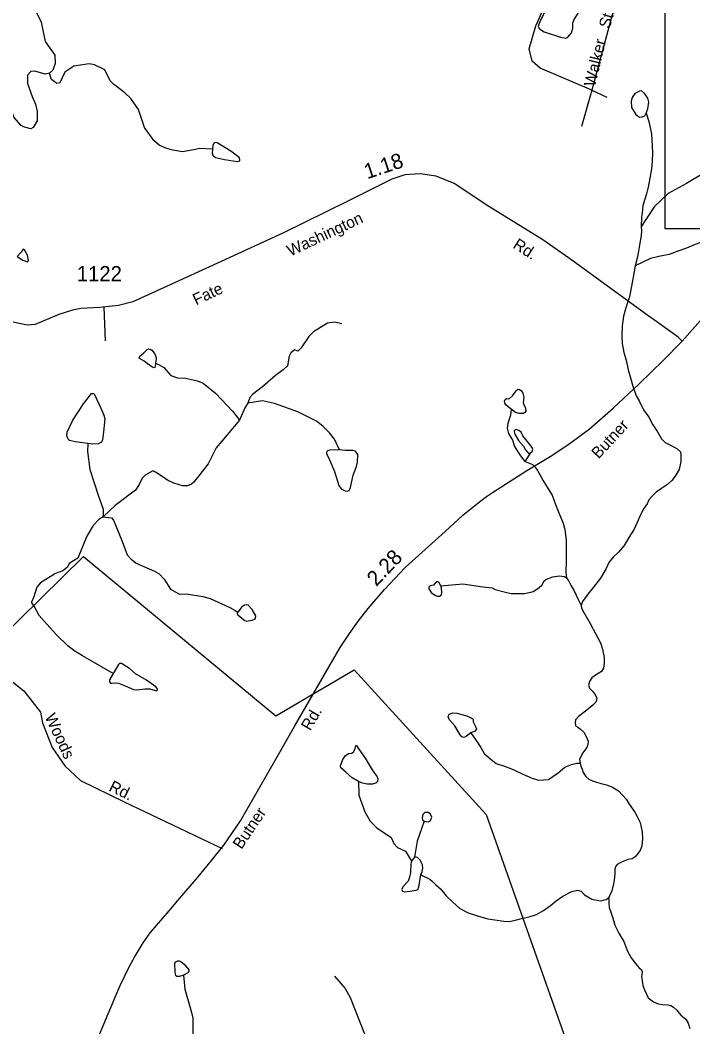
# Model space of a CAD drawing. Extents: x 2056842 to 2160602, y 826753 to 1016856.
# Drawn here: x 2070531 to 2076067, y 880850 to 889134 of the extents above; entities that cross this region are included whole.
import ezdxf

# ---------------------------------------------------------------- set-up
doc = ezdxf.new("R2010")
doc.units = 0
for name, color, linetype in [('Exist Boundary Land Use Reservation Military US Department of Defense', 7, 'Continuous'), ('Exist Hydrographic Creek Single Shore', 7, 'Continuous'), ('Exist Hydrographic Misc Water Feature', 7, 'Continuous'), ('Exist Road Non-System Type 51', 7, 'Continuous'), ('Exist Road Non-System Type 51 Label', 7, 'Continuous'), ('Exist Road Secondary Mileage Hundredths English Label', 7, 'Continuous'), ('Exist Road Secondary Type 51 Attributed', 7, 'Continuous'), ('Exist Road Secondary Type 51 Label', 7, 'Continuous'), ('Exist Road Secondary Type 51 Number Label', 7, 'Continuous'), ('Map Preparation Inset Cut Line', 7, 'Continuous')]:
    doc.layers.add(name, color=color, linetype=linetype)

msp = doc.modelspace()

# ---------------------------------------------------------------- linework, layer by layer
at = {"layer": 'Exist Boundary Land Use Reservation Military US Department of Defense'}
msp.add_lwpolyline([(2070346.7, 884029), (2071050.9, 884719.7), (2072633.6, 883408.7), (2073279.7, 883788.5), (2074366.8, 882597), (2075240.6, 880122.7)], dxfattribs=at)
at = {"layer": 'Exist Hydrographic Creek Single Shore'}
for points in [[(2070649.1, 889230.1), (2070703.2, 889116.2), (2070735.5, 888958.3), (2070815.8, 888844.4), (2070820, 888776.3), (2070800.1, 888722.3), (2070772.1, 888696.3)], [(2070772.1, 888696.3), (2070736, 888690.2), (2070652.1, 888714.2), (2070620, 888710), (2070592.2, 888680), (2070591.9, 888611.5), (2070628.6, 888506.4), (2070657.7, 888441.8), (2070670.4, 888382.2)], [(2070670.4, 888382.2), (2070671.7, 888304.9), (2070637.5, 888250.5), (2070619.7, 888240.3), (2070566.9, 888252.1), (2070538.8, 888265.8), (2070478.6, 888335.9), (2070443.7, 888441.8), (2070398.2, 888469.6), (2070341.2, 888465.8), (2070286.6, 888470.6)], [(2075682.4, 888367.8), (2075703.6, 888299.2), (2075726.5, 888197.5), (2075735.1, 888045.6), (2075731, 887969.5), (2075725.2, 887909.6), (2075711.7, 887833.7), (2075699.8, 887759.6), (2075684, 887703.5), (2075673.8, 887667.4), (2075656.1, 887609.6), (2075648.3, 887545.4), (2075644.2, 887513.2), (2075640.7, 887433.3)], [(2075640.7, 887433.3), (2075644.8, 887401.4), (2075640.7, 887357.5), (2075631.3, 887297.2), (2075619.2, 887233.3), (2075609.6, 887175.1), (2075591.7, 887113.3)], [(2075591.7, 887113.3), (2075574.3, 887018.9), (2075546.4, 886857.2), (2075514.8, 886767), (2075494.9, 886698.6), (2075485.3, 886616.9), (2075481.2, 886536.8), (2075483.7, 886472.7), (2075499.9, 886398.8), (2075518.1, 886334.8), (2075534.5, 886256.8), (2075552.6, 886189.2), (2075573.1, 886121.1), (2075599.1, 886043.3), (2075625.4, 886001.2), (2075659.4, 885927.4), (2075703.9, 885865.5), (2075737.7, 885803.6), (2075776.1, 885745.8), (2075808.1, 885687.8), (2075838.4, 885658.1), (2075878.4, 885640.2), (2075934.6, 885610.2), (2075964.5, 885580.5), (2075966.4, 885556.7), (2075966.8, 885500.6), (2075952.8, 885436.6), (2075921.3, 885382.5), (2075893.2, 885344.2), (2075857.3, 885312.3), (2075809.5, 885279.8), (2075765.4, 885249.9), (2075731.6, 885217.7), (2075703.7, 885185.4), (2075689.7, 885153.5), (2075663.9, 885115.6), (2075638.1, 885069.6), (2075584.6, 884945.4), (2075540.7, 884875.4), (2075500.9, 884810.8), (2075455, 884756.9), (2075411.5, 884714.8), (2075375.2, 884670.8), (2075353.7, 884622.6), (2075305.5, 884540.6), (2075250.1, 884468.3), (2075202.1, 884410.1), (2075158.7, 884350.2), (2075148.6, 884318.1)], [(2073177.2, 886633.4), (2073121.3, 886647.2), (2073061.2, 886639.3), (2072945.3, 886568.7), (2072905.5, 886530.6), (2072843.4, 886436.5), (2072815.3, 886410.7), (2072791.5, 886420.4), (2072759.6, 886396.5), (2072743.8, 886368.4), (2072732.1, 886290.3), (2072696.2, 886256.3), (2072632, 886210.1), (2072526.2, 886116.2), (2072442.3, 886053.7), (2072422.2, 886029.6), (2072404.4, 885981.7)], [(2072404.4, 885981.7), (2072380.2, 885943.9), (2072336.9, 885841.7)], [(2072336.9, 885841.7), (2072189.3, 885669.4), (2072145, 885615.2), (2072079.2, 885483.2), (2071959.4, 885330.8), (2071939.8, 885315.1), (2071907.8, 885301), (2071867.8, 885301), (2071795.8, 885324.9), (2071747.6, 885346.8), (2071643.7, 885414.5), (2071623.6, 885424.4), (2071559.8, 885390.3), (2071535.4, 885364.4), (2071511.4, 885312.4), (2071480, 885266), (2071311.9, 885139.7), (2071214.1, 885045.4)], [(2074683.6, 885500.6), (2074722.3, 885486.8), (2074746.1, 885478.1), (2074768.9, 885454.7), (2074789, 885426.8), (2074809, 885388.9), (2074833.2, 885348.7), (2074861.5, 885298.9), (2074907.5, 885225), (2074936.2, 885149.3), (2074968, 885065.3), (2075000.2, 884993.5), (2075012.3, 884943.4), (2075019, 884899.3), (2075022.9, 884851.6), (2075022.9, 884767.6), (2075023.1, 884679.6), (2075021.9, 884587.6), (2075026, 884543.6)], [(2071214.1, 885045.4), (2071178.2, 885023.7), (2071130.9, 884974.1), (2071080.8, 884887.5), (2071004.9, 884707.5), (2070935.2, 884661.2), (2070919.2, 884631.2), (2070882.9, 884603), (2070821.2, 884579.1), (2070697.9, 884504.1), (2070667.5, 884468.6), (2070642.2, 884387.6), (2070623.2, 884344.5)], [(2073993.9, 884479), (2074172.6, 884494), (2074338.2, 884471.3), (2074414.1, 884461.9), (2074440.2, 884449.8), (2074524.2, 884426.1), (2074572.2, 884416), (2074606.3, 884416.2), (2074638.2, 884414.5), (2074680.3, 884416.7), (2074720.3, 884422.8), (2074752.2, 884433), (2074782.4, 884450.7), (2074802.1, 884464.8), (2074824.2, 884485), (2074841.9, 884519.2), (2074857.8, 884531), (2074913.8, 884553.4), (2074965.7, 884561.3), (2075009.8, 884555.4), (2075026, 884543.6)], [(2075026, 884543.6), (2075037.9, 884527.6), (2075046.1, 884515.8), (2075066, 884477.9), (2075085.9, 884443.7), (2075126.3, 884360), (2075148.6, 884318.1)], [(2075148.6, 884318.1), (2075150.9, 884297.9), (2075158.5, 884278), (2075221, 884168.3), (2075269.2, 884082.3), (2075307.5, 884008.8), (2075323.9, 883956.7), (2075337.9, 883890.4), (2075335.8, 883842.5), (2075330.1, 883800.3), (2075314.5, 883772.7), (2075288.3, 883758.4), (2075264.5, 883742.5), (2075236.6, 883720.4), (2075216.5, 883692.2), (2075208.5, 883662.1), (2075216.5, 883636.2), (2075242.9, 883608.3), (2075262.8, 883582.4), (2075277.2, 883558.5), (2075274.9, 883538.5), (2075266.9, 883522.7), (2075247, 883498.5), (2075210.9, 883470.3), (2075183.1, 883448.1), (2075125.6, 883404.1), (2075101.5, 883376.1), (2075097.4, 883352), (2075101.9, 883328.1), (2075119.9, 883316.1), (2075141.8, 883298.1), (2075169.7, 883276), (2075189.6, 883240.1), (2075203.8, 883200.2), (2075202.1, 883174.2), (2075194.3, 883148.1), (2075162.4, 883104.3), (2075136.3, 883057.9), (2075134.7, 883050), (2075138.6, 883018.2)], [(2074240, 883269.2), (2074284.3, 883205.4), (2074322.3, 883147.3), (2074348.3, 883099.6), (2074390.7, 883063.9), (2074448.6, 883017.7), (2074516.8, 882994.1), (2074589, 882968.4), (2074668.6, 882928.8), (2074743.2, 882896.8), (2074796.7, 882878.9), (2074879, 882885.2), (2074913.2, 882909.2), (2074956.9, 882939.5), (2075012.5, 882987.8), (2075066.6, 883009.6), (2075110.5, 883020.1), (2075138.6, 883018.2)], [(2075138.6, 883018.2), (2075144.9, 882994.2), (2075155, 882970.3), (2075165, 882944), (2075187.1, 882909.8), (2075210.9, 882888.3), (2075240.9, 882874.5), (2075272.9, 882862.7), (2075312.9, 882852.6), (2075357.2, 882842.6), (2075404.9, 882820.8), (2075453.5, 882793.1), (2075487.4, 882757.1), (2075517.5, 882723.4), (2075543.5, 882681.2), (2075587.8, 882615.7), (2075607.7, 882579.4), (2075631.7, 882531.6), (2075648.3, 882455.6), (2075652.4, 882395.7), (2075646.5, 882339.8), (2075632.5, 882299.7), (2075602.8, 882263.7), (2075591.1, 882247.6), (2075566.7, 882233.4), (2075530.8, 882227.5), (2075492.9, 882211.4), (2075467.1, 882199.1), (2075443.1, 882185.2), (2075433, 882172.9), (2075425.2, 882149), (2075425.4, 882116.9), (2075421.3, 882074.9), (2075413.3, 882027), (2075399.8, 881969), (2075380.1, 881929), (2075374, 881912.9)], [(2073827.6, 882099.5), (2073901.7, 882063.9), (2073923.8, 882046.4), (2073950.1, 882020.5), (2073989.9, 881986.4), (2074036.4, 881928.7), (2074092, 881874.8), (2074148.4, 881822.8), (2074218.5, 881787.4), (2074294.4, 881763.7), (2074380.7, 881737.7), (2074436.7, 881730), (2074510.9, 881718.3), (2074558.5, 881716.4), (2074616.5, 881730.7), (2074668.6, 881744.7), (2074720.9, 881754.6), (2074780.8, 881774.8), (2074836.3, 881807.3), (2074896.4, 881849.3), (2074941.9, 881885.4), (2074996.3, 881925.5), (2075069.7, 881963.9), (2075117.7, 881974), (2075147.2, 881966.3), (2075174.6, 881935), (2075234.6, 881900), (2075305.8, 881887.5), (2075338.3, 881894.8), (2075354.3, 881898.9), (2075374, 881912.9)], [(2075374, 881912.9), (2075376.2, 881880.8), (2075374.2, 881864.9), (2075378.1, 881833.1), (2075392.2, 881792.9), (2075408.6, 881742.9), (2075424.8, 881686.8), (2075461.3, 881615.2), (2075497.4, 881551.3), (2075527.3, 881479.3), (2075559.5, 881417.6), (2075593.6, 881371.6), (2075621.5, 881337.6), (2075643.6, 881319.7), (2075648.1, 881305.7), (2075650.2, 881298.1), (2075643.8, 881267.7), (2075648.1, 881229.8), (2075656.3, 881189.9), (2075668.2, 881154), (2075684.4, 881117.9), (2075698.6, 881087.8), (2075742.6, 881054.4), (2075780.8, 881038.4), (2075816.7, 881034.2), (2075861, 881032.3), (2075886.6, 881026.4), (2075906.5, 881012.8), (2075931.1, 880988.8), (2075969, 880946.9), (2076009.2, 880912.9), (2076029.1, 880881.1), (2076041.4, 880835)], [(2073119, 881265.6), (2073205.1, 881165.6), (2073247.2, 881091.9), (2073363.8, 880792.2)]]:
    msp.add_lwpolyline(points, dxfattribs=at)
at = {"layer": 'Exist Hydrographic Misc Water Feature'}
msp.add_line((2074727.3, 885569.3), (2074683.6, 885500.6), dxfattribs=at)
for points in [[(2074816.7, 889137.7), (2074798, 889100.2), (2074794.3, 889081.5), (2074804.2, 889062.8), (2074844.1, 889037.8), (2074976.4, 888994.1), (2075020, 888985.4), (2075038.7, 888994.1), (2075067.4, 889030.3), (2075079.9, 889067.8), (2075079.9, 889110.2), (2075091.1, 889140.2), (2075127.3, 889198.8), (2075126.1, 889212.6), (2075117.3, 889220), (2075071.2, 889232.5), (2075006.3, 889256.2), (2074942.7, 889291.2), (2074919, 889302.4), (2074912.8, 889302.4), (2074905.3, 889294.9), (2074871.6, 889245), (2074816.7, 889137.7)], [(2072112.6, 888073.1), (2072006.8, 888077), (2071974.4, 888068.9), (2071866.8, 888050.7), (2071786.8, 888064.5), (2071730.8, 888080.3), (2071674.6, 888106.2), (2071630.5, 888142.2), (2071554.1, 888249.9), (2071506.1, 888398), (2071442.1, 888487.7), (2071393.5, 888536), (2071299.6, 888607.5), (2071271.7, 888635.6), (2071227.6, 888723.5), (2071143.1, 888767.2), (2071099.5, 888773.3), (2070971.5, 888755), (2070899.3, 888704.6), (2070857.7, 888616.9), (2070833.5, 888612.8), (2070787.8, 888646.5), (2070771.4, 888696.5)], [(2075682.4, 888367.8), (2075697.4, 888404), (2075704.9, 888458.9), (2075697.4, 888492.6), (2075667.5, 888531.3), (2075645, 888551.3), (2075627.5, 888550), (2075590.1, 888531.3), (2075566.4, 888496.4), (2075558.9, 888466.4), (2075562.7, 888415.2), (2075597.6, 888356.6), (2075626.3, 888336.6), (2075648.7, 888337.9), (2075671.2, 888346.6), (2075682.4, 888367.8)], [(2072112.6, 888073.1), (2072110, 888040.2), (2072115.1, 888023.7), (2072139.2, 888002.2), (2072212.6, 887986.9), (2072318.9, 887971.7), (2072339.2, 887976.8), (2072339.2, 887986.9), (2072332.9, 888003.4), (2072265.8, 888055.4), (2072151.8, 888123.8), (2072135.4, 888126.3), (2072124, 888121.2), (2072116.4, 888101), (2072112.6, 888073.1)], [(2076494, 887999.4), (2076460.3, 887985.6), (2076379.2, 887950.7), (2076350.5, 887940.7), (2076272, 887922), (2076156.4, 887873.3), (2076013, 887789.7), (2075863.3, 887707.3), (2075752.1, 887601.5), (2075668.6, 887475.4), (2075640.7, 887433.3)], [(2076163.2, 887313.9), (2076086.9, 887288.6), (2076013.3, 887256.4), (2075951.2, 887236.1), (2075871.4, 887204), (2075787.8, 887187.9), (2075717.2, 887173.4), (2075591.7, 887113.3)], [(2070592.4, 887200.3), (2070566.5, 887244.4), (2070554.4, 887248.3), (2070538.2, 887224.4)], [(2070538.2, 887224.4), (2070506.6, 887188.2), (2070552.2, 887158.1)], [(2070552.2, 887158.1), (2070592.4, 887144.3), (2070600.4, 887154.5), (2070592.4, 887200.3)], [(2071644.3, 886311.7), (2071643, 886288.3), (2071639.9, 886274.4), (2071632.9, 886273.1), (2071619, 886276.9), (2071589.8, 886298.4), (2071550.6, 886326.3), (2071512, 886349.7), (2071510.7, 886358), (2071515.8, 886368.7), (2071548.1, 886394.7), (2071576.5, 886423.9), (2071588.6, 886428.9), (2071601.2, 886427), (2071615.8, 886417.5), (2071637.3, 886389.6), (2071648.7, 886364.9), (2071650, 886345.9), (2071644.3, 886311.7)], [(2071644.3, 886311.7), (2071675.6, 886298.3), (2071714.2, 886276.6), (2071770, 886208.5), (2071825.9, 886190.7), (2071890.3, 886188.7), (2071990, 886167), (2072038, 886147.1), (2072138.4, 886063.4), (2072280.6, 885913.6), (2072336.9, 885841.7)], [(2074572.4, 885933.3), (2074532.4, 885962), (2074519.9, 885982), (2074517.4, 885999.5), (2074522.4, 886013.3), (2074532.4, 886019.5), (2074548.7, 886018.3), (2074558.7, 886019.5), (2074583.6, 886043.3), (2074612.4, 886083.3), (2074626.1, 886095.8), (2074639.9, 886094.5), (2074652.4, 886087), (2074668.6, 886063.3), (2074676.1, 886030.8), (2074672.4, 886005.8), (2074669.9, 885988.3), (2074674.9, 885970.8), (2074688.6, 885940.8), (2074691.1, 885917), (2074684.8, 885904.5), (2074669.9, 885895.8), (2074638.6, 885897), (2074606.1, 885905.8), (2074572.4, 885933.3)], [(2071087.5, 885648.8), (2070982.4, 885662.7), (2070938.1, 885674.1), (2070926.7, 885685.5), (2070915.3, 885712.1), (2070917.8, 885743.8), (2070963.4, 885841.4), (2071050.8, 885975.7), (2071117.9, 886060.6), (2071133.1, 886061.8), (2071141.9, 886054.2), (2071193.8, 885940.2), (2071219.2, 885883.2), (2071226.8, 885852.8), (2071215.4, 885745.1), (2071209, 885679.2), (2071198.9, 885660.2), (2071173.6, 885646.3), (2071129.3, 885643.7), (2071087.5, 885648.8)], [(2073158.3, 885597.5), (2073116.5, 885686.2), (2073076.8, 885737.2), (2073024.5, 885791), (2072968.5, 885834.8), (2072816.8, 885910.6), (2072624.4, 885978.3), (2072526.4, 886000), (2072404.4, 885981.7)], [(2074572.4, 885933.3), (2074564.9, 885884.5), (2074543.7, 885813.2), (2074539.9, 885775.7), (2074548.7, 885732), (2074582.4, 885678.2), (2074599.9, 885624.5), (2074626.1, 885582), (2074647.4, 885548.1), (2074683.6, 885500.6)], [(2074727.3, 885569.3), (2074744.8, 885584.3), (2074749.8, 885600.6), (2074743.6, 885616.8), (2074714.8, 885656.8), (2074668.6, 885713.1), (2074654.9, 885743.1), (2074634.9, 885755.6), (2074612.4, 885764.4), (2074596.1, 885758.1), (2074596.1, 885748.1), (2074602.4, 885728.1), (2074632.4, 885675.6), (2074672.4, 885629.3), (2074689.8, 885596.8), (2074707.3, 885576.8), (2074714.8, 885571.8), (2074727.3, 885569.3)], [(2071087.5, 885648.8), (2071085, 885582.9), (2071103.6, 885435.5), (2071175.7, 885215.6), (2071214.3, 885109.5), (2071214.1, 885045.4)], [(2073158.3, 885597.5), (2073076, 885595), (2073058.3, 885586.1), (2073050.7, 885574.7), (2073050.7, 885565.8), (2073072.2, 885530.3), (2073116.5, 885418.8), (2073153.3, 885304.8), (2073172.2, 885278.2), (2073205.2, 885260.5), (2073224.2, 885256.7), (2073238.1, 885264.3), (2073249.5, 885287.1), (2073271, 885389.7), (2073298.9, 885461.9), (2073307.7, 885497.4), (2073309, 885560.7), (2073290, 885586.1), (2073268.5, 885593.7), (2073207.7, 885593.7), (2073158.3, 885597.5)], [(2071214.1, 885045.4), (2071282.2, 885037.9), (2071300, 885017.8), (2071368.5, 884852), (2071412.6, 884734.1), (2071440.9, 884700.2), (2071485.2, 884664.3), (2071636.9, 884598.6), (2071674.8, 884576.6), (2071715.2, 884532.8), (2071767.3, 884452.7), (2071843.2, 884410.8), (2071899.2, 884413.2), (2072035.5, 884391.3), (2072095.4, 884373.3), (2072255.5, 884299.5), (2072299.6, 884275.7), (2072321.7, 884263.1)], [(2073993.9, 884479), (2073978.9, 884502.8), (2073970.2, 884511.5), (2073960.2, 884512.8), (2073945.2, 884501.5), (2073931.4, 884485.3), (2073905.2, 884477.8), (2073895.2, 884469), (2073895.2, 884455.3), (2073912.7, 884424), (2073948.9, 884399), (2073966.4, 884392.8), (2073981.4, 884394), (2073995.1, 884402.8), (2074001.4, 884421.5), (2073997.6, 884461.5), (2073993.9, 884479)], [(2071297, 883756.6), (2071043.6, 883902.3), (2070972.6, 883946.7), (2070923.3, 883984.7), (2070830.8, 884075.9), (2070749.8, 884164.6), (2070686.5, 884235.5), (2070646, 884312.8), (2070623.2, 884344.5)], [(2072321.7, 884263.1), (2072316.6, 884256.7), (2072316.6, 884249.1), (2072322.3, 884241.5), (2072355.9, 884213.7), (2072380.6, 884192.8), (2072394.5, 884189), (2072436.9, 884195.9), (2072462.2, 884204.8), (2072467.9, 884213), (2072469.8, 884232), (2072440.7, 884283.3), (2072406.5, 884319.5), (2072392, 884322), (2072376.8, 884319.5), (2072352.1, 884303), (2072333.1, 884276.4), (2072321.7, 884263.1)], [(2071297, 883756.6), (2071266.7, 883705.9), (2071265.4, 883689.5), (2071273, 883678.1), (2071288.2, 883676.8), (2071312.2, 883679.3), (2071341.4, 883676.8), (2071394.5, 883656.5), (2071462.9, 883626.1), (2071492, 883622.3), (2071556.6, 883632.5), (2071597.1, 883632.5), (2071645.2, 883618.5), (2071656.6, 883617.3), (2071660.4, 883619.8), (2071660.4, 883631.2), (2071647.8, 883648.9), (2071571.8, 883702.1), (2071480.6, 883755.4), (2071431.3, 883797.2), (2071364.1, 883839), (2071349, 883839), (2071338.8, 883832.6), (2071319.8, 883799.7), (2071297, 883756.6)], [(2074240, 883269.2), (2074203.8, 883240.5), (2074183.8, 883231.7), (2074165.1, 883236.7), (2074152.6, 883251.7), (2074107.6, 883326.7), (2074063.9, 883376.7), (2074053.9, 883401.8), (2074062.6, 883423), (2074092.6, 883434.3), (2074123.8, 883430.5), (2074206.3, 883409.3), (2074242.5, 883391.8), (2074257.5, 883380.5), (2074260, 883360.5), (2074277.5, 883320.5), (2074285, 883299.2), (2074271.3, 883284.2), (2074240, 883269.2)], [(2073316.1, 882869.8), (2073264.2, 882898.9), (2073213.5, 882942), (2073170.5, 882982.5), (2073167.9, 882997.7), (2073183.1, 883044.6), (2073205.9, 883080.1), (2073233.8, 883097.8), (2073261.6, 883102.9), (2073275.6, 883114.3), (2073288.2, 883139.6), (2073292, 883163.7), (2073298.4, 883163.7), (2073318.6, 883135.8), (2073370.5, 883061.1), (2073428.8, 882963.5), (2073468, 882907.8), (2073474.4, 882891.3), (2073470.6, 882869.8), (2073457.9, 882855.8), (2073431.3, 882846.9), (2073387, 882845.7), (2073347.7, 882855.8), (2073316.1, 882869.8)], [(2073316.1, 882869.8), (2073318.6, 882757), (2073366.5, 882619.8), (2073410.6, 882541.7), (2073466.6, 882488.2), (2073583, 882408.5), (2073604.8, 882358.5), (2073636.8, 882326.4), (2073700.7, 882294.4), (2073751.6, 882212.2)], [(2073856.7, 882541.6), (2073890.9, 882537.8), (2073907.4, 882548), (2073917.5, 882574.6), (2073908.7, 882598.6), (2073887.1, 882613.8), (2073860.5, 882613.8), (2073845.3, 882597.4), (2073837.7, 882570.8), (2073842.8, 882553), (2073856.7, 882541.6)], [(2073856.7, 882541.6), (2073797.2, 882378.2), (2073777, 882245.2)], [(2073751.6, 882212.2), (2073746.6, 882190.7), (2073742.8, 882121), (2073735.2, 882080.4), (2073722.5, 882048.8), (2073679.5, 882000.6), (2073673.1, 881980.4), (2073678.2, 881965.2), (2073695.9, 881960.1), (2073756.7, 881967.7), (2073788.4, 881974), (2073802.3, 881980.4), (2073812.4, 882001.9), (2073821.3, 882065.2), (2073827.6, 882099.5)], [(2073777, 882245.2), (2073751.6, 882212.2)], [(2073827.6, 882099.5), (2073837.7, 882128.6), (2073845.3, 882156.5), (2073841.5, 882181.8), (2073822.6, 882221.1), (2073801, 882242.6), (2073789.6, 882245.2), (2073777, 882245.2)], [(2071874.1, 881274.7), (2071841.2, 881264.5), (2071820.9, 881264.5), (2071812.1, 881274.7), (2071807, 881297.5), (2071804.5, 881374.7), (2071812.1, 881386.1), (2071827.2, 881393.7), (2071839.9, 881392.5), (2071855.1, 881386.1), (2071879.2, 881365.9), (2071918.4, 881317.7), (2071919.7, 881307.6), (2071909.5, 881293.7), (2071874.1, 881274.7)], [(2071874.1, 881274.7), (2071886.8, 881159.4), (2071932.3, 880998.5), (2071952.6, 880927.5), (2071951.3, 880739.3), (2071938.7, 880473.6), (2071922.5, 880425.3), (2071920.7, 880365.5), (2072051.4, 879953.9)]]:
    msp.add_lwpolyline(points, dxfattribs=at)
at = {"layer": 'Exist Road Non-System Type 51'}
for p, q in [((2075458.1, 889382.8), (2075234.7, 888557.1)), ((2075234.7, 888557.1), (2075149.8, 888257.5)), ((2075234.7, 888557.1), (2075359.8, 888500.4)), ((2071220.4, 886771.9), (2071231.5, 886495.8))]:
    msp.add_line(p, q, dxfattribs=at)
for points in [[(2075234.7, 888557.1), (2074810.1, 888737.4), (2074744.6, 888797), (2074720.8, 888898.4), (2074774.4, 889086.2), (2074915.9, 889403.7)], [(2069479.9, 884000.2), (2069824.6, 884008.2), (2070129.3, 883911.9), (2070345.7, 883783.6), (2070562.2, 883615.1), (2070698.5, 883438.6), (2070714.5, 883350.4), (2070794.7, 883149.8), (2070898.9, 882997.4), (2071027.2, 882877), (2071387.9, 882700.5), (2072191.9, 882318.6)]]:
    msp.add_lwpolyline(points, dxfattribs=at)
at = {"layer": 'Exist Road Secondary Type 51 Attributed'}
for points in [[(2075979.2, 886491.7), (2075946.3, 886524.6), (2075789.8, 886638.7), (2075676, 886717.3), (2075070.5, 887157.8), (2074832.9, 887325.5), (2074387.5, 887601.2), (2074102.2, 887788.3), (2073954.8, 887850.9), (2073823.7, 887868.8), (2073695.6, 887861.3), (2073590.6, 887826.3), (2073228.6, 887644.5), (2072696.8, 887383.6), (2072185.2, 887148.8), (2071457.5, 886815.7), (2071341.3, 886785.9), (2071186.4, 886768), (2071029.2, 886759.8), (2070960.7, 886747.9), (2070849, 886712.1), (2070653.9, 886630.1), (2070588.3, 886622.7), (2070472.1, 886649.5)], [(2075979.2, 886491.7), (2076148.3, 886684.1), (2076279.1, 886838.9), (2076457.2, 887044.4), (2076569.8, 887153.7)], [(2071091.8, 880563.5), (2071313.2, 881095.3), (2071353.8, 881189.1), (2071428.2, 881342.6), (2071472.4, 881424.5), (2071542.6, 881542.2), (2071601.8, 881622.2), (2071755.9, 881804.5), (2071829.4, 881889.9), (2071995.2, 882082.9), (2072095.6, 882204.2), (2072207.3, 882344), (2072343.5, 882545.3), (2072612.7, 883014), (2072791.6, 883326.3), (2073164.8, 883971.5), (2073242.1, 884087.4), (2073314.4, 884190.8), (2073394.7, 884292.9), (2073528.3, 884447.7), (2073700.1, 884628.3), (2074027, 884927.1), (2074174.2, 885060.1), (2074311, 885170.7), (2074369.6, 885213.1), (2074417.4, 885246), (2074699.6, 885428.7), (2074891.7, 885543.5), (2075036.4, 885640.3), (2075213.5, 885768.6), (2075409.8, 885942), (2075620.9, 886137.5), (2075824.2, 886336.4), (2075979.2, 886491.7)]]:
    msp.add_lwpolyline(points, dxfattribs=at)
at = {"layer": 'Map Preparation Inset Cut Line'}
msp.add_lwpolyline([(2075837.6, 899339.2), (2086885.8, 899339.2), (2086885.8, 887416.1), (2075837.6, 887416.1), (2075837.6, 899339.2)], dxfattribs=at)

# ---------------------------------------------------------------- texts
at = {"layer": 'Exist Road Non-System Type 51 Label'}
for s, rotation, p in [('St.', 73.50513, (2075381.2, 889059.9)), ('Walker', 76.54283, (2075261, 888580.8)), ('Woods', 294.94576, (2070731.4, 883402.2)), ('Rd.', 333.73583, (2071253.6, 882796.2))]:
    msp.add_text(s, height=95, rotation=rotation, dxfattribs=at).set_placement(p)
at = {"layer": 'Exist Road Secondary Mileage Hundredths English Label'}
for s, rotation, p in [('1.18', 18.44663, (2073386.3, 887824.1)), ('2.28', 46.43424, (2073461.6, 884468.3))]:
    msp.add_text(s, height=125, rotation=rotation, dxfattribs=at).set_placement(p)
at = {"layer": 'Exist Road Secondary Type 51 Label'}
for s, rotation, p in [('Washington', 25.13456, (2072754.5, 887187.6)), ('Rd.', 327.49273, (2074578.4, 887263.9)), ('Fate', 25.04107, (2071978.7, 886785.3)), ('Butner', 47.24977, (2075291.4, 885518.5)), ('Rd.', 59.73786, (2072918.5, 883279.7)), ('Butner', 56.05021, (2072351.6, 882304.7))]:
    msp.add_text(s, height=95, rotation=rotation, dxfattribs=at).set_placement(p)
at = {"layer": 'Exist Road Secondary Type 51 Number Label'}
msp.add_text('1122', height=125, dxfattribs=at).set_placement((2070996.4, 886985.2))

doc.saveas('drawing.dxf')
